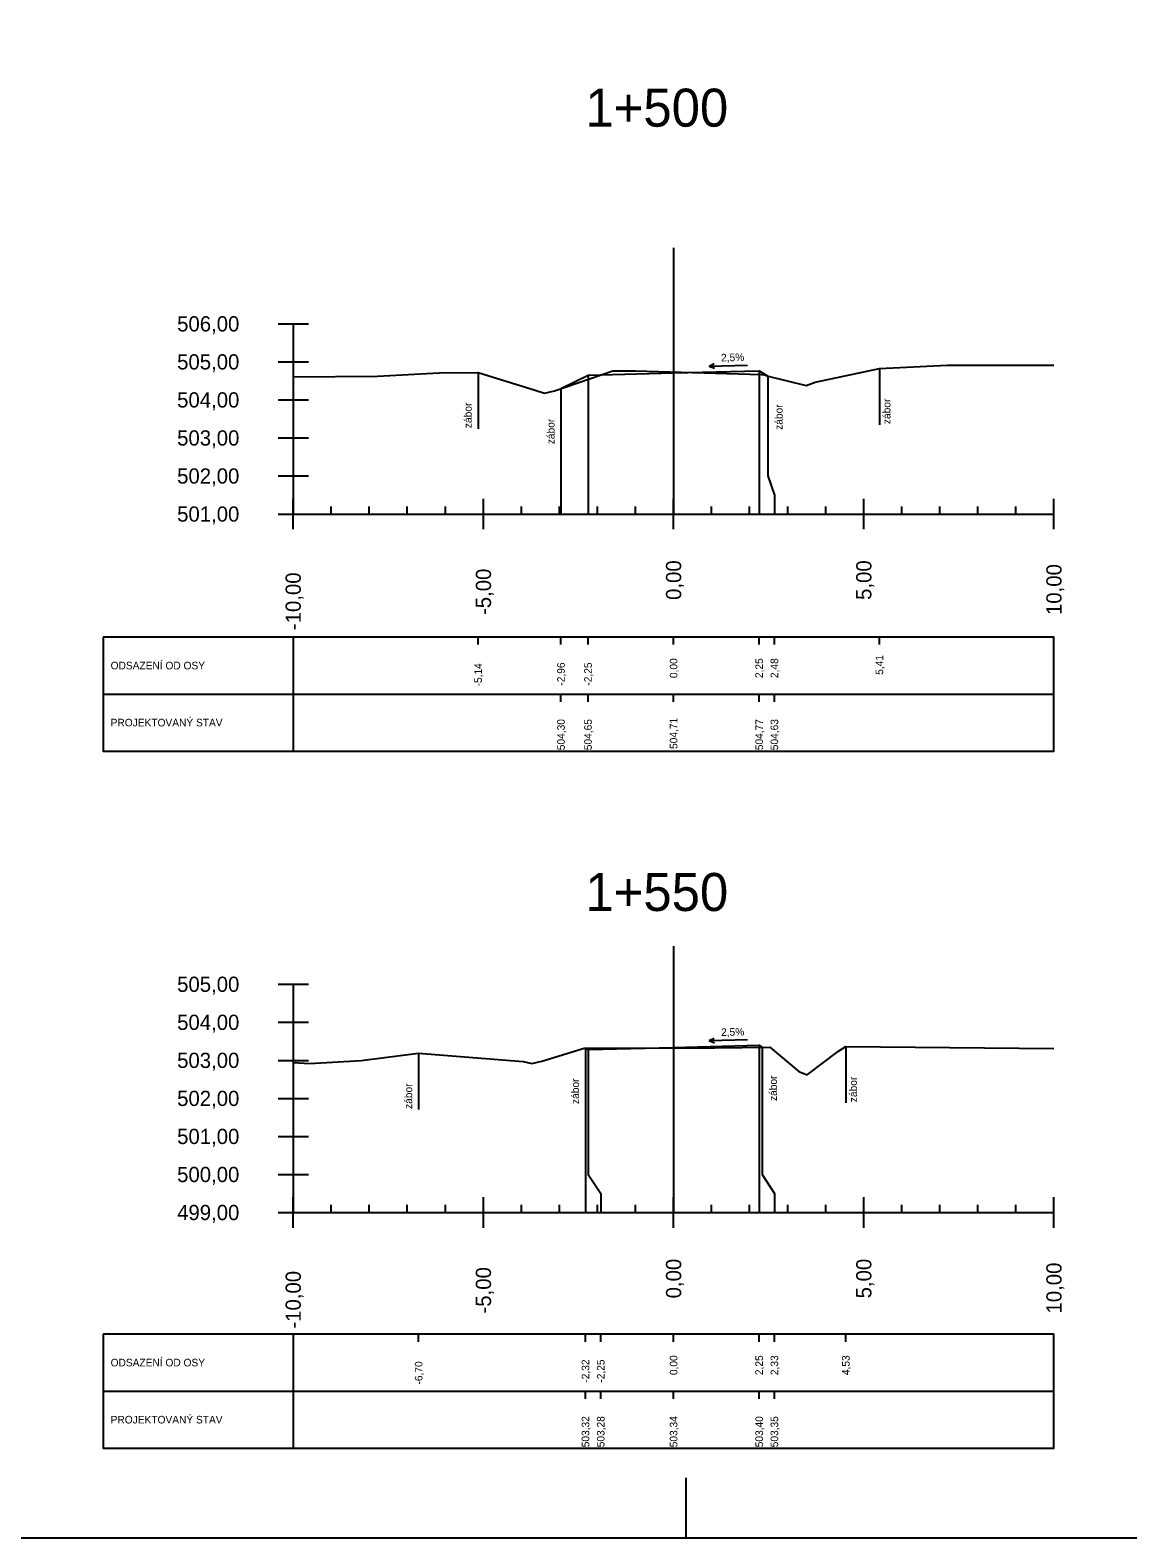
# Model space of a CAD drawing. Extents: x -631407 to -631215, y -1089700 to -1088598.
# Drawn here: x -631316.63 to -631287.77, y -1089270.8 to -1089231.17 of the extents above; entities that cross this region are included whole.
import ezdxf

# ---------------------------------------------------------------- set-up
doc = ezdxf.new("R2010")
doc.units = 0
for name, color, linetype in [('08_LEGENDA_HV', 7, 'Continuous'), ('59', 7, 'Continuous'), ('DTM-Breaklines', 7, 'Continuous'), ('NIVELETA_VYSKY', 7, 'Continuous'), ('REZ_BODY', 7, 'Continuous'), ('REZ_ODSTUPY', 7, 'Continuous'), ('REZ_POPIS', 7, 'Continuous'), ('REZ_RAMY', 7, 'Continuous'), ('REZ_STANICENI', 7, 'Continuous'), ('REZ_SVISLE', 7, 'Continuous'), ('REZ_TENKA', 7, 'Continuous'), ('REZ_TLUSTA', 7, 'Continuous'), ('TABULKA_POPIS', 7, 'Continuous'), ('TEREN', 7, 'Continuous'), ('zábor', 7, 'Continuous')]:
    doc.layers.add(name, color=color, linetype=linetype)

msp = doc.modelspace()

# ---------------------------------------------------------------- linework, layer by layer
at = {"layer": '08_LEGENDA_HV'}
msp.add_lwpolyline([(-631215.384, -1089270.801), (-631215.384, -1089110.964), (-631407.014, -1089110.964), (-631407.014, -1089270.801)], close=True, dxfattribs=at)
at = {"layer": '59'}
for p, q in [((-631310.116, -1089238.886), (-631309.316, -1089238.886)), ((-631309.716, -1089238.886), (-631309.716, -1089243.886)), ((-631310.116, -1089239.886), (-631309.316, -1089239.886)), ((-631310.116, -1089240.886), (-631309.316, -1089240.886)), ((-631310.116, -1089241.886), (-631309.316, -1089241.886)), ((-631310.116, -1089242.886), (-631309.316, -1089242.886)), ((-631310.116, -1089243.886), (-631309.316, -1089243.886)), ((-631310.116, -1089256.248), (-631309.316, -1089256.248)), ((-631309.716, -1089256.248), (-631309.716, -1089262.248)), ((-631310.116, -1089257.248), (-631309.316, -1089257.248)), ((-631310.116, -1089258.248), (-631309.316, -1089258.248)), ((-631310.116, -1089259.248), (-631309.316, -1089259.248)), ((-631310.116, -1089260.248), (-631309.316, -1089260.248)), ((-631310.116, -1089261.248), (-631309.316, -1089261.248)), ((-631310.116, -1089262.248), (-631309.316, -1089262.248))]:
    msp.add_line(p, q, dxfattribs=at)
at = {"layer": 'DTM-Breaklines'}
msp.add_line((-631299.384, -1089270.801), (-631299.384, -1089269.221), dxfattribs=at)
at = {"layer": 'REZ_RAMY'}
for p, q in [((-631314.716, -1089247.119), (-631314.716, -1089250.119)), ((-631309.716, -1089247.119), (-631309.716, -1089250.119)), ((-631304.855, -1089247.319), (-631304.855, -1089247.119)), ((-631302.676, -1089247.319), (-631302.676, -1089247.119)), ((-631301.966, -1089247.319), (-631301.966, -1089247.119)), ((-631299.716, -1089247.319), (-631299.716, -1089247.119)), ((-631297.466, -1089247.319), (-631297.466, -1089247.119)), ((-631297.066, -1089247.319), (-631297.066, -1089247.119)), ((-631294.306, -1089247.319), (-631294.306, -1089247.119)), ((-631314.716, -1089248.619), (-631289.716, -1089248.619)), ((-631302.676, -1089248.819), (-631302.676, -1089248.619)), ((-631301.966, -1089248.819), (-631301.966, -1089248.619)), ((-631299.716, -1089248.819), (-631299.716, -1089248.619)), ((-631297.466, -1089248.819), (-631297.466, -1089248.619)), ((-631297.066, -1089248.819), (-631297.066, -1089248.619)), ((-631314.716, -1089265.444), (-631314.716, -1089268.444)), ((-631309.716, -1089265.444), (-631309.716, -1089268.444)), ((-631306.418, -1089265.644), (-631306.418, -1089265.444)), ((-631302.032, -1089265.644), (-631302.032, -1089265.444)), ((-631301.632, -1089265.644), (-631301.632, -1089265.444)), ((-631299.716, -1089265.644), (-631299.716, -1089265.444)), ((-631297.466, -1089265.644), (-631297.466, -1089265.444)), ((-631297.066, -1089265.644), (-631297.066, -1089265.444)), ((-631295.188, -1089265.644), (-631295.188, -1089265.444)), ((-631314.716, -1089266.944), (-631289.716, -1089266.944)), ((-631302.032, -1089267.144), (-631302.032, -1089266.944)), ((-631301.632, -1089267.144), (-631301.632, -1089266.944)), ((-631299.716, -1089267.144), (-631299.716, -1089266.944)), ((-631297.466, -1089267.144), (-631297.466, -1089266.944)), ((-631297.066, -1089267.144), (-631297.066, -1089266.944))]:
    msp.add_line(p, q, dxfattribs=at)
for points in [[(-631314.716, -1089247.119), (-631314.716, -1089250.119), (-631289.716, -1089250.119), (-631289.716, -1089247.119)], [(-631314.716, -1089265.444), (-631314.716, -1089268.444), (-631289.716, -1089268.444), (-631289.716, -1089265.444)]]:
    msp.add_lwpolyline(points, close=True, dxfattribs=at)
at = {"layer": 'REZ_SVISLE'}
for points in [[(-631297.466, -1089240.119), (-631297.466, -1089242.886), (-631297.466, -1089243.386), (-631297.466, -1089243.886)], [(-631301.966, -1089240.232), (-631301.966, -1089242.886), (-631301.966, -1089243.386), (-631301.966, -1089243.886)], [(-631299.716, -1089240.176), (-631299.716, -1089242.886), (-631299.716, -1089243.386), (-631299.716, -1089243.886)], [(-631297.234, -1089240.258), (-631297.234, -1089242.886), (-631297.066, -1089243.386), (-631297.066, -1089243.886)], [(-631302.676, -1089240.587), (-631302.676, -1089242.886), (-631302.676, -1089243.386), (-631302.676, -1089243.886)], [(-631302.032, -1089257.931), (-631302.032, -1089261.248), (-631302.032, -1089261.748), (-631302.032, -1089262.248)], [(-631301.966, -1089257.964), (-631301.966, -1089261.248), (-631301.632, -1089261.748), (-631301.632, -1089262.248)], [(-631299.716, -1089257.908), (-631299.716, -1089261.248), (-631299.716, -1089261.748), (-631299.716, -1089262.248)], [(-631297.466, -1089257.852), (-631297.466, -1089261.248), (-631297.466, -1089261.748), (-631297.466, -1089262.248)], [(-631297.383, -1089257.902), (-631297.383, -1089261.248), (-631297.066, -1089261.748), (-631297.066, -1089262.248)]]:
    msp.add_lwpolyline(points, dxfattribs=at)
at = {"layer": 'REZ_TENKA'}
for p, q in [((-631308.716, -1089243.886), (-631308.716, -1089243.686)), ((-631307.716, -1089243.886), (-631307.716, -1089243.686)), ((-631306.716, -1089243.886), (-631306.716, -1089243.686)), ((-631305.716, -1089243.886), (-631305.716, -1089243.686)), ((-631303.716, -1089243.886), (-631303.716, -1089243.686)), ((-631302.716, -1089243.886), (-631302.716, -1089243.686)), ((-631301.716, -1089243.886), (-631301.716, -1089243.686)), ((-631300.716, -1089243.886), (-631300.716, -1089243.686)), ((-631298.716, -1089243.886), (-631298.716, -1089243.686)), ((-631297.716, -1089243.886), (-631297.716, -1089243.686)), ((-631296.716, -1089243.886), (-631296.716, -1089243.686)), ((-631295.716, -1089243.886), (-631295.716, -1089243.686)), ((-631293.716, -1089243.886), (-631293.716, -1089243.686)), ((-631292.716, -1089243.886), (-631292.716, -1089243.686)), ((-631291.716, -1089243.886), (-631291.716, -1089243.686)), ((-631290.716, -1089243.886), (-631290.716, -1089243.686)), ((-631308.716, -1089262.248), (-631308.716, -1089262.048)), ((-631307.716, -1089262.248), (-631307.716, -1089262.048)), ((-631306.716, -1089262.248), (-631306.716, -1089262.048)), ((-631305.716, -1089262.248), (-631305.716, -1089262.048)), ((-631303.716, -1089262.248), (-631303.716, -1089262.048)), ((-631302.716, -1089262.248), (-631302.716, -1089262.048)), ((-631301.716, -1089262.248), (-631301.716, -1089262.048)), ((-631300.716, -1089262.248), (-631300.716, -1089262.048)), ((-631298.716, -1089262.248), (-631298.716, -1089262.048)), ((-631297.716, -1089262.248), (-631297.716, -1089262.048)), ((-631296.716, -1089262.248), (-631296.716, -1089262.048)), ((-631295.716, -1089262.248), (-631295.716, -1089262.048)), ((-631293.716, -1089262.248), (-631293.716, -1089262.048)), ((-631292.716, -1089262.248), (-631292.716, -1089262.048)), ((-631291.716, -1089262.248), (-631291.716, -1089262.048)), ((-631290.716, -1089262.248), (-631290.716, -1089262.048))]:
    msp.add_line(p, q, dxfattribs=at)
at = {"layer": 'REZ_TLUSTA'}
for p, q in [((-631299.716, -1089236.886), (-631299.716, -1089243.886)), ((-631309.716, -1089244.286), (-631309.716, -1089243.486)), ((-631304.716, -1089244.286), (-631304.716, -1089243.486)), ((-631299.716, -1089244.286), (-631299.716, -1089243.486)), ((-631294.716, -1089244.286), (-631294.716, -1089243.486)), ((-631289.716, -1089244.286), (-631289.716, -1089243.486)), ((-631309.716, -1089243.886), (-631289.716, -1089243.886)), ((-631299.716, -1089255.248), (-631299.716, -1089262.248)), ((-631309.716, -1089262.648), (-631309.716, -1089261.848)), ((-631304.716, -1089262.648), (-631304.716, -1089261.848)), ((-631299.716, -1089262.648), (-631299.716, -1089261.848)), ((-631294.716, -1089262.648), (-631294.716, -1089261.848)), ((-631289.716, -1089262.648), (-631289.716, -1089261.848)), ((-631309.716, -1089262.248), (-631289.716, -1089262.248))]:
    msp.add_line(p, q, dxfattribs=at)
at = {"layer": 'TEREN'}
for points in [[(-631309.716, -1089240.28), (-631307.504, -1089240.258), (-631305.882, -1089240.178), (-631304.855, -1089240.164), (-631303.357, -1089240.632), (-631303.111, -1089240.711), (-631302.85, -1089240.646), (-631301.311, -1089240.121), (-631300.72, -1089240.121), (-631297.413, -1089240.216), (-631297.325, -1089240.226), (-631297.23, -1089240.26), (-631296.232, -1089240.504), (-631295.997, -1089240.42), (-631294.306, -1089240.058), (-631292.525, -1089239.969), (-631289.716, -1089239.97)], [(-631302.676, -1089240.587), (-631301.966, -1089240.232), (-631299.716, -1089240.176), (-631297.466, -1089240.119), (-631297.234, -1089240.258)], [(-631309.716, -1089258.302), (-631309.285, -1089258.327), (-631307.933, -1089258.255), (-631306.418, -1089258.062), (-631303.674, -1089258.281), (-631303.443, -1089258.334), (-631303.18, -1089258.272), (-631302.065, -1089257.931), (-631298.634, -1089257.921), (-631297.19, -1089257.899), (-631296.421, -1089258.544), (-631296.204, -1089258.632), (-631295.379, -1089258.007), (-631295.188, -1089257.883), (-631289.716, -1089257.935)], [(-631302.032, -1089257.931), (-631301.966, -1089257.964), (-631299.716, -1089257.908), (-631297.466, -1089257.852), (-631297.383, -1089257.902)]]:
    msp.add_lwpolyline(points, dxfattribs=at)
at = {"layer": 'zábor'}
for p, q in [((-631298.783, -1089239.996), (-631298.646, -1089239.932)), ((-631298.783, -1089239.996), (-631297.775, -1089239.971)), ((-631298.783, -1089239.996), (-631298.643, -1089240.054)), ((-631294.306, -1089240.058), (-631294.306, -1089241.539)), ((-631304.855, -1089240.164), (-631304.855, -1089241.645)), ((-631298.783, -1089257.728), (-631298.646, -1089257.664)), ((-631298.783, -1089257.728), (-631297.775, -1089257.703)), ((-631298.783, -1089257.728), (-631298.643, -1089257.786)), ((-631295.188, -1089257.883), (-631295.188, -1089259.364)), ((-631306.418, -1089258.062), (-631306.418, -1089259.542))]:
    msp.add_line(p, q, dxfattribs=at)

# ---------------------------------------------------------------- texts
at = {"layer": 'NIVELETA_VYSKY'}
for s, p in [('504,71', (-631299.616, -1089250.062)), ('504,30', (-631302.576, -1089250.095)), ('504,65', (-631301.866, -1089250.095)), ('504,77', (-631297.366, -1089250.095)), ('504,63', (-631296.966, -1089250.095)), ('503,32', (-631301.932, -1089268.42)), ('503,28', (-631301.532, -1089268.42)), ('503,34', (-631299.616, -1089268.42)), ('503,40', (-631297.366, -1089268.42)), ('503,35', (-631296.966, -1089268.42))]:
    msp.add_text(s, height=0.2, rotation=90, dxfattribs=at).set_placement(p)
at = {"layer": 'REZ_BODY'}
for s, p in [('5,41', (-631294.206, -1089248.113)), ('-5,14', (-631304.755, -1089248.418)), ('-2,96', (-631302.576, -1089248.397)), ('-2,25', (-631301.866, -1089248.397)), ('0,00', (-631299.616, -1089248.199)), ('2,25', (-631297.366, -1089248.199)), ('2,48', (-631296.966, -1089248.199)), ('-6,70', (-631306.318, -1089266.77)), ('-2,32', (-631301.932, -1089266.721)), ('-2,25', (-631301.532, -1089266.721)), ('0,00', (-631299.616, -1089266.523)), ('2,25', (-631297.366, -1089266.523)), ('2,33', (-631296.966, -1089266.523)), ('4,53', (-631295.088, -1089266.523))]:
    msp.add_text(s, height=0.2, rotation=90, dxfattribs=at).set_placement(p)
at = {"layer": 'REZ_ODSTUPY'}
for s, p in [('0,00', (-631299.516, -1089246.144)), ('5,00', (-631294.516, -1089246.144)), ('10,00', (-631289.516, -1089246.541)), ('-10,00', (-631309.516, -1089246.938)), ('-5,00', (-631304.516, -1089246.541)), ('0,00', (-631299.516, -1089264.506)), ('5,00', (-631294.516, -1089264.506)), ('-10,00', (-631309.516, -1089265.3)), ('-5,00', (-631304.516, -1089264.903)), ('10,00', (-631289.516, -1089264.903))]:
    msp.add_text(s, height=0.4, rotation=90, dxfattribs=at).set_placement(p)
at = {"layer": 'REZ_POPIS'}
for s, p in [('506,00', (-631312.768, -1089239.086)), ('505,00', (-631312.768, -1089240.086)), ('504,00', (-631312.768, -1089241.086)), ('503,00', (-631312.768, -1089242.086)), ('502,00', (-631312.768, -1089243.086)), ('501,00', (-631312.768, -1089244.086)), ('505,00', (-631312.768, -1089256.448)), ('504,00', (-631312.768, -1089257.448)), ('503,00', (-631312.768, -1089258.448)), ('502,00', (-631312.768, -1089259.448)), ('501,00', (-631312.768, -1089260.448)), ('500,00', (-631312.768, -1089261.448)), ('499,00', (-631312.768, -1089262.448))]:
    msp.add_text(s, height=0.4, dxfattribs=at).set_placement(p)
at = {"layer": 'REZ_STANICENI'}
for s, p in [('1+500', (-631302.035, -1089233.703)), ('1+550', (-631302.035, -1089254.322))]:
    msp.add_text(s, height=1, dxfattribs=at).set_placement(p)
at = {"layer": 'TABULKA_POPIS'}
for s, p in [('ODSAZENÍ OD OSY', (-631314.516, -1089247.969)), ('PROJEKTOVANÝ STAV', (-631314.516, -1089249.469)), ('ODSAZENÍ OD OSY', (-631314.516, -1089266.294)), ('PROJEKTOVANÝ STAV', (-631314.516, -1089267.794))]:
    msp.add_text(s, height=0.2, dxfattribs=at).set_placement(p)
at = {"layer": 'zábor'}
for s, rotation, p in [('2,5%', 1.4321, (-631298.466, -1089239.875)), ('zábor', 90, (-631294.014, -1089241.522)), ('zábor', 90, (-631305.025, -1089241.627)), ('zábor', 90, (-631296.851, -1089241.673)), ('zábor', 90, (-631302.846, -1089242.051)), ('2,5%', 1.4321, (-631298.466, -1089257.608)), ('zábor', 90, (-631302.202, -1089259.395)), ('zábor', 90, (-631297, -1089259.316)), ('zábor', 90, (-631294.895, -1089259.347)), ('zábor', 90, (-631306.588, -1089259.525))]:
    msp.add_text(s, height=0.2, rotation=rotation, dxfattribs=at).set_placement(p)

doc.saveas('drawing.dxf')
